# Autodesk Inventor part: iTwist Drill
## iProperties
Author: Jeffrey G. Howard
Shininess: 85.0
PropertySet Name: _Private Model Information
Created: 2001-08
Part Number: iTwist Drill
Document SubType Name: Modeling
Designer: Jeffrey G. Howard
Control State: 0
Master: False
Checked Out: False
PropertySet Name: Design Tracking Control
Density: 0.0
Volumn: 0.0
Area: 0.0
PropertySet Name: Model Information
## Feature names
1. Extrusion1
2. Coil1
3. Extrusion2[blend]
4. Coil2
5. Extrusion3[blend]
6. Extrusion4[ptAngle]
7. Extrusion5[lipRelief]
8. Extrusion6[lipRelief]
9. Coil3
10. Coil4
11. Coil5
12. Coil6
